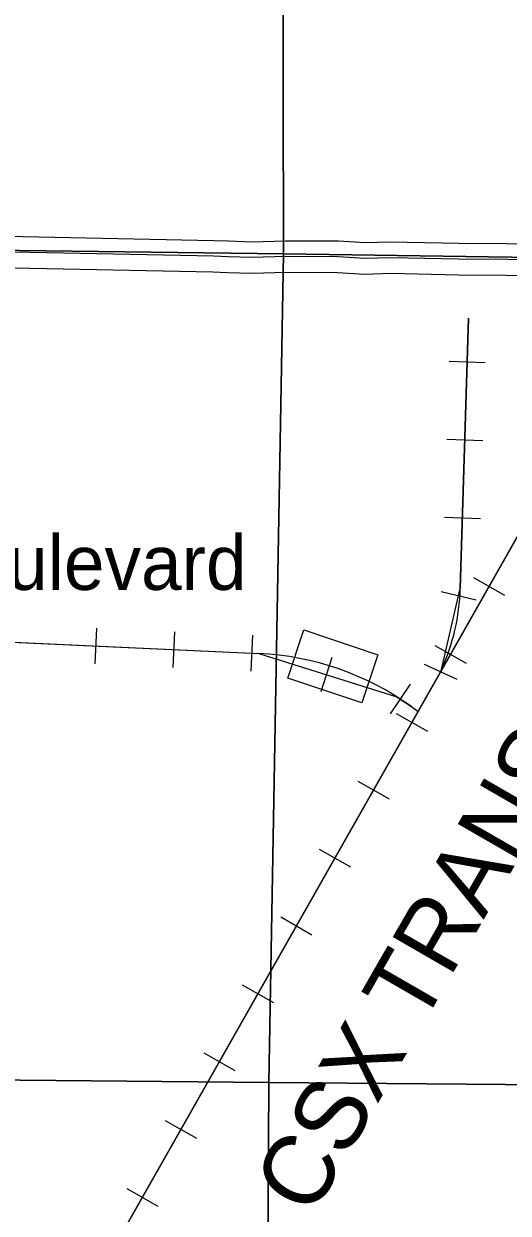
# Model space of a CAD drawing. Extents: x 380424 to 701066, y 1117407 to 1412949.
# Drawn here: x 487038 to 490144, y 1288311 to 1295930 of the extents above; entities that cross this region are included whole.
import ezdxf

# ---------------------------------------------------------------- set-up
doc = ezdxf.new("R2010")
doc.units = 0
for name, color, linetype in [('Railroad Stations', 7, 'Continuous'), ('Railroads', 7, 'Continuous'), ('Railroads Text', 7, 'Continuous'), ('Section Lines', 7, 'Continuous'), ('US Route Divided Highway Outline and Fill', 7, 'Continuous'), ('US Routes Highway Center Lines', 7, 'Continuous')]:
    doc.layers.add(name, color=color, linetype=linetype)

msp = doc.modelspace()

# ---------------------------------------------------------------- linework, layer by layer
at = {"layer": 'Railroad Stations'}
msp.add_lwpolyline([(489205, 1291580.6), (488730.7, 1291738.8), (488833.6, 1292047.1), (489307.9, 1291888.9)], close=True, dxfattribs=at)
at = {"layer": 'Railroads'}
for p, q in [((489889.4, 1294045.4), (489836.3, 1292312)), ((489765.8, 1293768.3), (489995.7, 1293761.3)), ((489750.5, 1293268.5), (489980.4, 1293261.5)), ((489735.3, 1292768.8), (489965.2, 1292761.7)), ((489920.1, 1292382.7), (490120.1, 1292269.1)), ((489713.8, 1292292.7), (489937.9, 1292240.7)), ((483503.6, 1292129.7), (488544.2, 1291896.1)), ((487504.6, 1292059.4), (487494, 1291829.7)), ((488004.1, 1292036.3), (487993.4, 1291806.5)), ((488503.5, 1292013.1), (488492.9, 1291783.4)), ((489673.1, 1291947.9), (489873.1, 1291834.3)), ((489011.8, 1291870.3), (488943.1, 1291650.8)), ((489605.5, 1291827.9), (489815, 1291733)), ((489716, 1291793), (489710.3, 1291780.5)), ((489515.5, 1291700.1), (489387.4, 1291509.1)), ((489426.2, 1291513.1), (489626.2, 1291399.6)), ((489522.8, 1291556.7), (489565.8, 1291526)), ((489179.3, 1291078.4), (489379.3, 1290964.8)), ((488932.3, 1290643.6), (489132.3, 1290530)), ((488685.4, 1290208.8), (488885.4, 1290095.2)), ((488438.5, 1289774.1), (488638.5, 1289660.5)), ((488191.5, 1289339.3), (488391.5, 1289225.7)), ((487944.6, 1288904.5), (488144.6, 1288790.9)), ((487697.7, 1288469.8), (487897.7, 1288356.2))]:
    msp.add_line(p, q, dxfattribs=at)
for points in [[(497553.8, 1305549.8), (492356.7, 1296439.9), (485366.2, 1284131.9)], [(488044.6, 1288847.7), (491007.8, 1294065)], [(489710.3, 1291780.5), (489716, 1291793), (489836.3, 1292312), (489889.4, 1294045.4)], [(483503.6, 1292129.7), (488544.2, 1291896.1), (489430.4, 1291618.8), (489451.5, 1291604.6)], [(489451.5, 1291604.6), (489522.8, 1291556.7), (489565.8, 1291526)], [(484960.7, 1283739), (485092.1, 1283796.4), (485366.2, 1284131.9), (485366.2, 1284131.9), (488044.6, 1288847.7)]]:
    msp.add_lwpolyline(points, dxfattribs=at)
for centre, radius, start, end in [((488478.6, 1292353.5), 1358.4, 335.63095, 358.24832), ((488459.7, 1290071.8), 1826.3, 54.39902, 87.34717)]:
    msp.add_arc(centre, radius, start, end, dxfattribs=at)
at = {"layer": 'Section Lines'}
for points in [[(484459.5, 1299798.3), (488691.4, 1299739.1), (488703.5, 1294456.6), (481245.5, 1294550.5)], [(481245.5, 1294550.5), (488703.5, 1294456.6), (488609.6, 1289147.4), (484280.2, 1289189.7)], [(484280.2, 1289189.7), (488609.6, 1289147.4), (488579.9, 1283894.9), (483277.3, 1283906.6), (483296.4, 1285187.6)]]:
    msp.add_lwpolyline(points, dxfattribs=at)
for points in [[(494038.1, 1299648.9), (493962.3, 1294380.5), (488703.5, 1294456.6), (488691.4, 1299739.1), (494025.8, 1299648.3)], [(493962.3, 1294380.5), (493911.1, 1289104.5), (488609.6, 1289147.4), (488703.5, 1294456.6)], [(493911.1, 1289104.5), (493911.1, 1289094.8), (493893, 1287694.2), (493874.7, 1283834.6), (488579.9, 1283894.9), (488609.6, 1289147.4)]]:
    msp.add_lwpolyline(points, close=True, dxfattribs=at)
at = {"layer": 'US Route Divided Highway Outline and Fill'}
for points in [[(492553.6, 1294303.4), (492555, 1294503.4), (489827.6, 1294522.2), (489389.6, 1294531.7), (489225.8, 1294527), (489056.5, 1294537.8), (488718.8, 1294538.6), (488499.9, 1294532.3), (488351.4, 1294537.7), (488256, 1294540.8), (486007.4, 1294586.7), (485476.7, 1294566.9)], [(485484.1, 1294367), (486009.1, 1294386.6), (488250.7, 1294340.9), (488344.4, 1294337.8), (488499.1, 1294332.2), (488721.5, 1294338.6), (489049.9, 1294337.8), (489222.3, 1294326.9), (489390.3, 1294331.7), (489824.7, 1294322.2), (492553.6, 1294303.4)]]:
    msp.add_lwpolyline(points, dxfattribs=at)
at = {"layer": 'US Routes Highway Center Lines'}
msp.add_lwpolyline([(492654.3, 1294403), (489826.1, 1294422.2), (489390, 1294431.7), (489224, 1294427), (489053.2, 1294437.8), (488720.1, 1294438.6), (488499.5, 1294432.2), (488347.9, 1294437.7), (488253.3, 1294440.9), (486008.3, 1294486.6), (485480.4, 1294466.9)], dxfattribs=at)

# ---------------------------------------------------------------- texts
at = {"layer": 'Railroads Text'}
for s, height, rotation, p in [('Boulevard', 350, 0.00019, (486358.7, 1292303.9)), ('CSX TRANS.', 450, 60.0604, (488884.1, 1288277.4))]:
    msp.add_text(s, height=height, rotation=rotation, dxfattribs=at).set_placement(p)

doc.saveas('drawing.dxf')
